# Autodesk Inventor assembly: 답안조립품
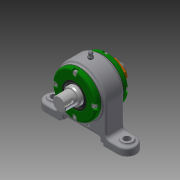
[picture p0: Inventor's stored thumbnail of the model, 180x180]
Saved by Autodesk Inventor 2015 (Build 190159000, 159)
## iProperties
Created: 2019-05
Part Number: 답안조립품
Document SubType Name: Assembly
Designer: now
Author: now
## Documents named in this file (13)
- C:\Users\now\Desktop\490504V1047\490504V1047\답안조립품.iam
- C:\Users\now\Desktop\490504V1047\490504V1047\개스킷.ipt
- C:\Users\now\Desktop\490504V1047\490504V1047\그리스니플 M6.ipt
- 그리스니플  M6.ipt
- C:\Users\now\Desktop\490504V1047\490504V1047\그리스니플개스킷.ipt
- C:\Users\now\Desktop\490504V1047\490504V1047\베어링너트.ipt
- C:\Users\now\Desktop\490504V1047\490504V1047\본체.ipt
- C:\Users\now\Desktop\490504V1047\490504V1047\볼트 M4.ipt
- C:\Users\now\Desktop\490504V1047\490504V1047\앵귤러 볼 베어링 7205.ipt
- C:\Users\now\Desktop\490504V1047\490504V1047\오일 실 28 40 5 B.ipt
- C:\Users\now\Desktop\490504V1047\490504V1047\축.ipt
- C:\Users\now\Desktop\490504V1047\490504V1047\칼라.ipt
- C:\Users\now\Desktop\490504V1047\490504V1047\커버.ipt
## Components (4 placed, 3 different names)
1. 개스킷:1
2. 그리스니플  M6:1
3. 그리스니플개스킷:1
4. 개스킷:2
